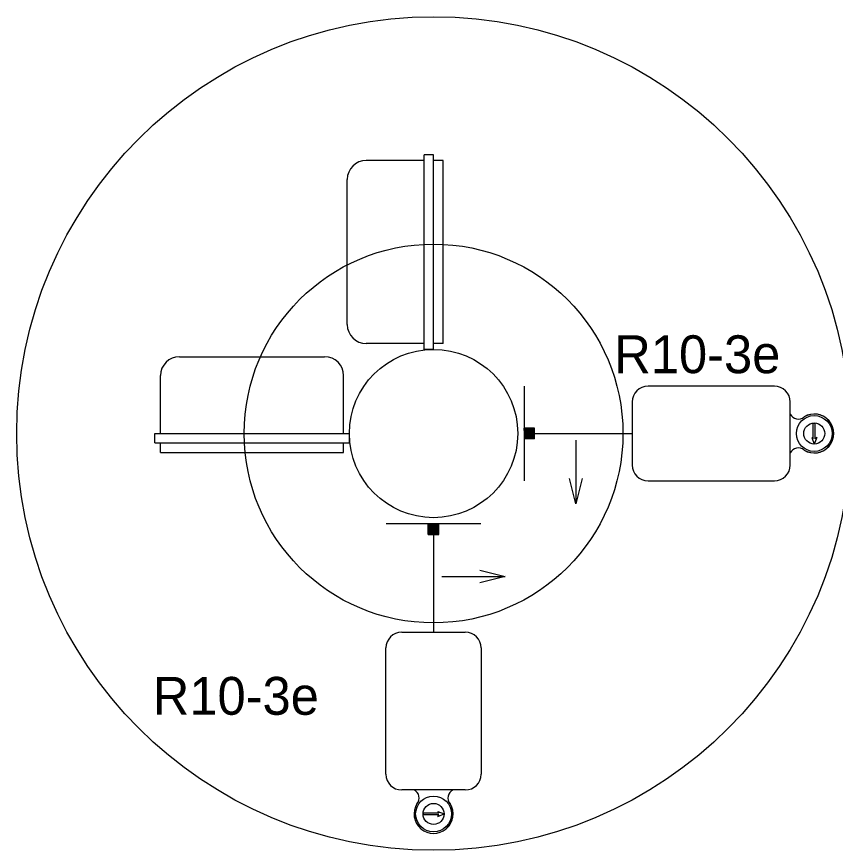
# Model space of a CAD drawing. Extents: x 418532 to 420296, y -565948 to -565286.
# Drawn here: x 419563.2 to 419660.5, y -565610 to -565510.9 of the extents above; entities that cross this region are included whole.
import ezdxf

# ---------------------------------------------------------------- set-up
doc = ezdxf.new("R2010")
doc.units = 0
doc.layers.add('T_Drafting', color=7, linetype='Continuous')

msp = doc.modelspace()

# ---------------------------------------------------------------- linework, layer by layer
at = {"layer": 'T_Drafting'}
for p, q in [((419611.639, -565550.436), (419611.639, -565527.311)), ((419612.764, -565527.311), (419611.639, -565527.311)), ((419612.764, -565550.436), (419612.764, -565527.311)), ((419611.639, -565527.998), (419604.764, -565527.998)), ((419613.889, -565527.998), (419612.764, -565527.998)), ((419613.889, -565549.748), (419613.889, -565527.998)), ((419602.514, -565547.498), (419602.514, -565530.248)), ((419611.639, -565549.748), (419604.764, -565549.748)), ((419612.764, -565550.436), (419611.639, -565550.436)), ((419613.889, -565549.748), (419612.764, -565549.748)), ((419582.576, -565551.311), (419599.826, -565551.311)), ((419580.326, -565560.436), (419580.326, -565553.561)), ((419602.076, -565560.436), (419602.076, -565553.561)), ((419623.514, -565554.811), (419623.514, -565566.061)), ((419653.266, -565554.811), (419638.243, -565554.811)), ((419636.368, -565556.686), (419636.368, -565564.186)), ((419655.141, -565564.186), (419655.141, -565556.686)), ((419657.879, -565559.195), (419658.104, -565559.195)), ((419657.879, -565561.077), (419657.879, -565559.195)), ((419658.104, -565561.077), (419658.104, -565559.195)), ((419579.639, -565560.436), (419602.764, -565560.436)), ((419579.639, -565561.561), (419579.639, -565560.436)), ((419602.764, -565561.561), (419602.764, -565560.436)), ((419624.764, -565559.811), (419623.514, -565559.811)), ((419623.514, -565561.056), (419624.759, -565559.811)), ((419623.514, -565561.035), (419624.738, -565559.811)), ((419623.514, -565561.014), (419624.717, -565559.811)), ((419623.514, -565560.993), (419624.696, -565559.811)), ((419623.514, -565560.972), (419624.675, -565559.811)), ((419623.514, -565560.95), (419624.653, -565559.811)), ((419623.514, -565560.929), (419624.632, -565559.811)), ((419623.514, -565560.908), (419624.611, -565559.811)), ((419623.514, -565560.887), (419624.59, -565559.811)), ((419623.514, -565560.866), (419624.568, -565559.811)), ((419623.514, -565560.844), (419624.547, -565559.811)), ((419623.514, -565560.823), (419624.526, -565559.811)), ((419623.514, -565560.802), (419624.505, -565559.811)), ((419623.514, -565560.781), (419624.484, -565559.811)), ((419623.514, -565560.759), (419624.462, -565559.811)), ((419623.514, -565560.738), (419624.441, -565559.811)), ((419623.514, -565560.717), (419624.42, -565559.811)), ((419623.514, -565560.696), (419624.399, -565559.811)), ((419623.514, -565560.675), (419624.378, -565559.811)), ((419623.514, -565560.653), (419624.356, -565559.811)), ((419623.514, -565560.632), (419624.335, -565559.811)), ((419623.514, -565560.611), (419624.314, -565559.811)), ((419623.514, -565560.59), (419624.293, -565559.811)), ((419623.514, -565560.569), (419624.271, -565559.811)), ((419623.514, -565560.547), (419624.25, -565559.811)), ((419623.514, -565560.526), (419624.229, -565559.811)), ((419623.514, -565560.505), (419624.208, -565559.811)), ((419623.514, -565560.484), (419624.187, -565559.811)), ((419623.514, -565560.463), (419624.165, -565559.811)), ((419623.514, -565560.441), (419624.144, -565559.811)), ((419623.514, -565560.42), (419624.123, -565559.811)), ((419623.514, -565560.399), (419624.102, -565559.811)), ((419623.514, -565560.378), (419624.081, -565559.811)), ((419623.514, -565560.356), (419624.059, -565559.811)), ((419623.514, -565560.335), (419624.038, -565559.811)), ((419623.514, -565560.314), (419624.017, -565559.811)), ((419623.514, -565560.293), (419623.996, -565559.811)), ((419623.514, -565560.272), (419623.974, -565559.811)), ((419623.514, -565560.25), (419623.953, -565559.811)), ((419623.514, -565560.229), (419623.932, -565559.811)), ((419623.514, -565560.208), (419623.911, -565559.811)), ((419623.514, -565560.187), (419623.89, -565559.811)), ((419623.514, -565560.166), (419623.868, -565559.811)), ((419623.514, -565560.144), (419623.847, -565559.811)), ((419623.514, -565560.123), (419623.826, -565559.811)), ((419623.514, -565560.102), (419623.805, -565559.811)), ((419623.514, -565560.081), (419623.784, -565559.811)), ((419623.514, -565560.059), (419623.762, -565559.811)), ((419623.514, -565560.038), (419623.741, -565559.811)), ((419623.514, -565560.017), (419623.72, -565559.811)), ((419623.514, -565559.996), (419623.699, -565559.811)), ((419623.514, -565559.975), (419623.677, -565559.811)), ((419623.514, -565559.953), (419623.656, -565559.811)), ((419623.514, -565559.932), (419623.635, -565559.811)), ((419623.514, -565559.911), (419623.614, -565559.811)), ((419623.514, -565559.89), (419623.593, -565559.811)), ((419623.514, -565559.869), (419623.571, -565559.811)), ((419623.514, -565559.847), (419623.55, -565559.811)), ((419623.514, -565559.826), (419623.529, -565559.811)), ((419623.531, -565561.061), (419624.764, -565559.828)), ((419623.552, -565561.061), (419624.764, -565559.849)), ((419623.573, -565561.061), (419624.764, -565559.87)), ((419623.594, -565561.061), (419624.764, -565559.891)), ((419623.615, -565561.061), (419624.764, -565559.913)), ((419623.637, -565561.061), (419624.764, -565559.934)), ((419623.658, -565561.061), (419624.764, -565559.955)), ((419623.679, -565561.061), (419624.764, -565559.976)), ((419623.7, -565561.061), (419624.764, -565559.997)), ((419623.721, -565561.061), (419624.764, -565560.019)), ((419623.743, -565561.061), (419624.764, -565560.04)), ((419623.764, -565561.061), (419624.764, -565560.061)), ((419623.785, -565561.061), (419624.764, -565560.082)), ((419623.806, -565561.061), (419624.764, -565560.103)), ((419623.828, -565561.061), (419624.764, -565560.125)), ((419623.849, -565561.061), (419624.764, -565560.146)), ((419623.87, -565561.061), (419624.764, -565560.167)), ((419623.891, -565561.061), (419624.764, -565560.188)), ((419623.912, -565561.061), (419624.764, -565560.21)), ((419623.934, -565561.061), (419624.764, -565560.231)), ((419623.955, -565561.061), (419624.764, -565560.252)), ((419623.976, -565561.061), (419624.764, -565560.273)), ((419623.997, -565561.061), (419624.764, -565560.294)), ((419624.018, -565561.061), (419624.764, -565560.316)), ((419624.04, -565561.061), (419624.764, -565560.337)), ((419624.061, -565561.061), (419624.764, -565560.358)), ((419624.082, -565561.061), (419624.764, -565560.379)), ((419624.103, -565561.061), (419624.764, -565560.4)), ((419624.125, -565561.061), (419624.764, -565560.422)), ((419624.764, -565561.061), (419624.764, -565559.811)), ((419624.764, -565560.436), (419636.368, -565560.436)), ((419624.764, -565561.061), (419623.514, -565561.061)), ((419624.146, -565561.061), (419624.764, -565560.443)), ((419624.167, -565561.061), (419624.764, -565560.464)), ((419624.188, -565561.061), (419624.764, -565560.485)), ((419624.209, -565561.061), (419624.764, -565560.507)), ((419624.231, -565561.061), (419624.764, -565560.528)), ((419624.252, -565561.061), (419624.764, -565560.549)), ((419624.273, -565561.061), (419624.764, -565560.57)), ((419624.294, -565561.061), (419624.764, -565560.591)), ((419624.315, -565561.061), (419624.764, -565560.613)), ((419624.337, -565561.061), (419624.764, -565560.634)), ((419624.358, -565561.061), (419624.764, -565560.655)), ((419624.379, -565561.061), (419624.764, -565560.676)), ((419624.4, -565561.061), (419624.764, -565560.697)), ((419624.422, -565561.061), (419624.764, -565560.719)), ((419624.443, -565561.061), (419624.764, -565560.74)), ((419624.464, -565561.061), (419624.764, -565560.761)), ((419624.485, -565561.061), (419624.764, -565560.782)), ((419624.506, -565561.061), (419624.764, -565560.803)), ((419624.528, -565561.061), (419624.764, -565560.825)), ((419624.549, -565561.061), (419624.764, -565560.846)), ((419624.57, -565561.061), (419624.764, -565560.867)), ((419624.591, -565561.061), (419624.764, -565560.888)), ((419624.612, -565561.061), (419624.764, -565560.91)), ((419624.634, -565561.061), (419624.764, -565560.931)), ((419624.655, -565561.061), (419624.764, -565560.952)), ((419624.676, -565561.061), (419624.764, -565560.973)), ((419624.697, -565561.061), (419624.764, -565560.994)), ((419624.719, -565561.061), (419624.764, -565561.016)), ((419624.74, -565561.061), (419624.764, -565561.037)), ((419624.761, -565561.061), (419624.764, -565561.058)), ((419629.679, -565561.235), (419629.679, -565568.785)), ((419657.691, -565560.927), (419657.991, -565561.686)), ((419657.879, -565561.077), (419657.691, -565560.927)), ((419658.291, -565560.927), (419657.991, -565561.686)), ((419658.291, -565560.927), (419658.104, -565561.077)), ((419579.639, -565561.561), (419602.764, -565561.561)), ((419580.326, -565562.686), (419580.326, -565561.561)), ((419602.076, -565562.686), (419602.076, -565561.561)), ((419580.326, -565562.686), (419602.076, -565562.686)), ((419638.243, -565566.061), (419653.266, -565566.061)), ((419618.389, -565571.186), (419607.139, -565571.186)), ((419612.139, -565572.436), (419612.139, -565571.186)), ((419612.139, -565572.427), (419613.38, -565571.186)), ((419612.139, -565572.406), (419613.359, -565571.186)), ((419612.139, -565572.384), (419613.337, -565571.186)), ((419612.139, -565572.363), (419613.316, -565571.186)), ((419612.139, -565572.342), (419613.295, -565571.186)), ((419612.139, -565572.321), (419613.274, -565571.186)), ((419612.139, -565572.3), (419613.252, -565571.186)), ((419612.139, -565572.278), (419613.231, -565571.186)), ((419612.139, -565572.257), (419613.21, -565571.186)), ((419612.139, -565572.236), (419613.189, -565571.186)), ((419612.139, -565572.215), (419613.168, -565571.186)), ((419612.139, -565572.194), (419613.146, -565571.186)), ((419612.139, -565572.172), (419613.125, -565571.186)), ((419612.139, -565572.151), (419613.104, -565571.186)), ((419612.139, -565572.13), (419613.083, -565571.186)), ((419612.139, -565572.109), (419613.062, -565571.186)), ((419612.139, -565572.087), (419613.04, -565571.186)), ((419612.139, -565572.066), (419613.019, -565571.186)), ((419612.139, -565572.045), (419612.998, -565571.186)), ((419612.139, -565572.024), (419612.977, -565571.186)), ((419612.139, -565572.003), (419612.955, -565571.186)), ((419612.139, -565571.981), (419612.934, -565571.186)), ((419612.139, -565571.96), (419612.913, -565571.186)), ((419612.139, -565571.939), (419612.892, -565571.186)), ((419612.139, -565571.918), (419612.871, -565571.186)), ((419612.139, -565571.897), (419612.849, -565571.186)), ((419612.139, -565571.875), (419612.828, -565571.186)), ((419612.139, -565571.854), (419612.807, -565571.186)), ((419612.139, -565571.833), (419612.786, -565571.186)), ((419612.139, -565571.812), (419612.765, -565571.186)), ((419612.139, -565571.79), (419612.743, -565571.186)), ((419612.139, -565571.769), (419612.722, -565571.186)), ((419612.139, -565571.748), (419612.701, -565571.186)), ((419612.139, -565571.727), (419612.68, -565571.186)), ((419612.139, -565571.706), (419612.659, -565571.186)), ((419612.139, -565571.684), (419612.637, -565571.186)), ((419612.139, -565571.663), (419612.616, -565571.186)), ((419612.139, -565571.642), (419612.595, -565571.186)), ((419612.139, -565571.621), (419612.574, -565571.186)), ((419612.139, -565571.6), (419612.552, -565571.186)), ((419612.139, -565571.578), (419612.531, -565571.186)), ((419612.139, -565571.557), (419612.51, -565571.186)), ((419612.139, -565571.536), (419612.489, -565571.186)), ((419612.139, -565571.515), (419612.468, -565571.186)), ((419612.139, -565571.493), (419612.446, -565571.186)), ((419612.139, -565571.472), (419612.425, -565571.186)), ((419612.139, -565571.451), (419612.404, -565571.186)), ((419612.139, -565571.43), (419612.383, -565571.186)), ((419612.139, -565571.409), (419612.362, -565571.186)), ((419612.139, -565571.387), (419612.34, -565571.186)), ((419612.139, -565571.366), (419612.319, -565571.186)), ((419612.139, -565571.345), (419612.298, -565571.186)), ((419612.139, -565571.324), (419612.277, -565571.186)), ((419612.139, -565571.303), (419612.255, -565571.186)), ((419612.139, -565571.281), (419612.234, -565571.186)), ((419612.139, -565571.26), (419612.213, -565571.186)), ((419612.139, -565571.239), (419612.192, -565571.186)), ((419612.139, -565571.218), (419612.171, -565571.186)), ((419612.139, -565571.197), (419612.149, -565571.186)), ((419612.151, -565572.436), (419613.389, -565571.198)), ((419612.172, -565572.436), (419613.389, -565571.219)), ((419612.193, -565572.436), (419613.389, -565571.241)), ((419612.215, -565572.436), (419613.389, -565571.262)), ((419612.236, -565572.436), (419613.389, -565571.283)), ((419612.257, -565572.436), (419613.389, -565571.304)), ((419612.278, -565572.436), (419613.389, -565571.325)), ((419613.389, -565572.436), (419613.389, -565571.186)), ((419612.299, -565572.436), (419613.389, -565571.347)), ((419612.321, -565572.436), (419613.389, -565571.368)), ((419612.342, -565572.436), (419613.389, -565571.389)), ((419612.363, -565572.436), (419613.389, -565571.41)), ((419612.384, -565572.436), (419613.389, -565571.431)), ((419612.406, -565572.436), (419613.389, -565571.453)), ((419612.427, -565572.436), (419613.389, -565571.474)), ((419612.448, -565572.436), (419613.389, -565571.495)), ((419612.469, -565572.436), (419613.389, -565571.516)), ((419612.49, -565572.436), (419613.389, -565571.537)), ((419612.512, -565572.436), (419613.389, -565571.559)), ((419612.533, -565572.436), (419613.389, -565571.58)), ((419612.554, -565572.436), (419613.389, -565571.601)), ((419612.575, -565572.436), (419613.389, -565571.622)), ((419612.596, -565572.436), (419613.389, -565571.644)), ((419612.618, -565572.436), (419613.389, -565571.665)), ((419612.639, -565572.436), (419613.389, -565571.686)), ((419612.66, -565572.436), (419613.389, -565571.707)), ((419612.681, -565572.436), (419613.389, -565571.728)), ((419612.703, -565572.436), (419613.389, -565571.75)), ((419612.724, -565572.436), (419613.389, -565571.771)), ((419612.745, -565572.436), (419613.389, -565571.792)), ((419612.766, -565572.436), (419613.389, -565571.813)), ((419612.787, -565572.436), (419613.389, -565571.834)), ((419612.809, -565572.436), (419613.389, -565571.856)), ((419612.83, -565572.436), (419613.389, -565571.877)), ((419612.851, -565572.436), (419613.389, -565571.898)), ((419612.872, -565572.436), (419613.389, -565571.919)), ((419612.893, -565572.436), (419613.389, -565571.941)), ((419612.915, -565572.436), (419613.389, -565571.962)), ((419612.936, -565572.436), (419613.389, -565571.983)), ((419612.957, -565572.436), (419613.389, -565572.004)), ((419612.978, -565572.436), (419613.389, -565572.025)), ((419613, -565572.436), (419613.389, -565572.047)), ((419613.021, -565572.436), (419613.389, -565572.068)), ((419613.042, -565572.436), (419613.389, -565572.089)), ((419613.063, -565572.436), (419613.389, -565572.11)), ((419613.084, -565572.436), (419613.389, -565572.131)), ((419613.106, -565572.436), (419613.389, -565572.153)), ((419613.127, -565572.436), (419613.389, -565572.174)), ((419613.148, -565572.436), (419613.389, -565572.195)), ((419613.169, -565572.436), (419613.389, -565572.216)), ((419613.19, -565572.436), (419613.389, -565572.238)), ((419613.212, -565572.436), (419613.389, -565572.259)), ((419613.233, -565572.436), (419613.389, -565572.28)), ((419613.254, -565572.436), (419613.389, -565572.301)), ((419613.275, -565572.436), (419613.389, -565572.322)), ((419612.139, -565572.436), (419613.389, -565572.436)), ((419612.764, -565572.436), (419612.764, -565584.04)), ((419613.296, -565572.436), (419613.389, -565572.344)), ((419613.318, -565572.436), (419613.389, -565572.365)), ((419613.339, -565572.436), (419613.389, -565572.386)), ((419613.36, -565572.436), (419613.389, -565572.407)), ((419613.381, -565572.436), (419613.389, -565572.428)), ((419613.73, -565577.437), (419621.28, -565577.437)), ((419608.989, -565584.04), (419616.538, -565584.04)), ((419607.114, -565600.915), (419607.114, -565585.915)), ((419618.413, -565585.915), (419618.413, -565600.915)), ((419616.538, -565602.79), (419608.989, -565602.79)), ((419611.523, -565605.527), (419611.523, -565605.752)), ((419613.405, -565605.527), (419611.523, -565605.527)), ((419613.405, -565605.752), (419611.523, -565605.752)), ((419613.255, -565605.34), (419614.014, -565605.64)), ((419613.405, -565605.527), (419613.255, -565605.34)), ((419613.255, -565605.94), (419614.014, -565605.64)), ((419613.255, -565605.94), (419613.405, -565605.752))]:
    msp.add_line(p, q, dxfattribs=at)
for points in [[(419630.429, -565565.785), (419629.679, -565568.785), (419628.929, -565565.785)], [(419618.28, -565576.687), (419621.28, -565577.437), (419618.28, -565578.187)]]:
    msp.add_lwpolyline(points, dxfattribs=at)
for centre, radius in [((419612.764, -565560.436), 49.525), ((419612.764, -565560.436), 22.5), ((419612.764, -565560.436), 10), ((419657.991, -565560.436), 2.125), ((419657.991, -565560.436), 1.25), ((419612.764, -565605.64), 2.125), ((419612.764, -565605.64), 1.25)]:
    msp.add_circle(centre, radius, dxfattribs=at)
for centre, radius, start, end in [((419604.764, -565530.248), 2.25, 90, 180), ((419604.764, -565547.498), 2.25, 180, 270), ((419582.576, -565553.561), 2.25, 90, 180), ((419599.826, -565553.561), 2.25, 360, 90), ((419638.243, -565556.686), 1.875, 90, 180), ((419653.266, -565556.686), 1.875, 0, 90), ((419656.091, -565557.676), 1.05, 205.19558, 311.80279), ((419657.991, -565560.436), 2.312, 238.74024, 121.25976), ((419657.991, -565560.436), 2.312, 42.50664, 121.25976), ((419656.091, -565563.195), 1.05, 48.19721, 154.80442), ((419657.991, -565560.436), 2.312, 238.74024, 317.49336), ((419638.243, -565564.186), 1.875, 180, 270), ((419653.266, -565564.186), 1.875, 270, 0), ((419608.989, -565585.915), 1.875, 90, 180), ((419616.538, -565585.915), 1.875, 0, 90), ((419608.989, -565600.915), 1.875, 180, 270), ((419616.538, -565600.915), 1.875, 270, 0), ((419610.004, -565603.74), 1.05, 318.19721, 64.80442), ((419615.523, -565603.74), 1.05, 115.19558, 221.80279), ((419612.764, -565605.64), 2.312, 148.74024, 227.49336), ((419612.764, -565605.64), 2.312, 148.74024, 31.25976), ((419612.764, -565605.64), 2.312, 312.50664, 31.25976)]:
    msp.add_arc(centre, radius, start, end, dxfattribs=at)

# ---------------------------------------------------------------- texts
for p in [(419634.23, -565553.271), (419579.406, -565593.856)]:
    msp.add_text('R10-3e', height=4.5, dxfattribs=at).set_placement(p)

doc.saveas('drawing.dxf')
